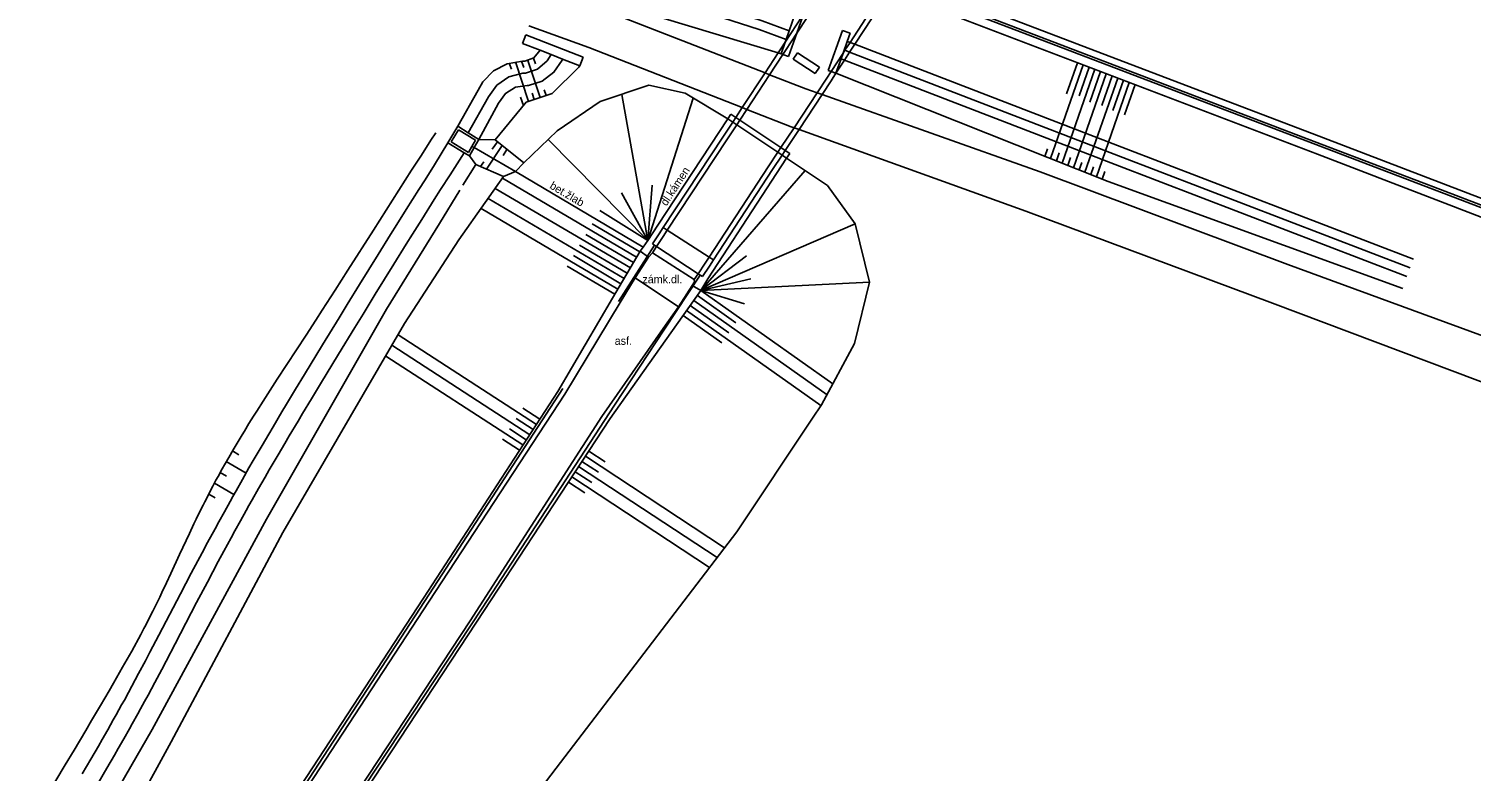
# Model space of a CAD drawing. Extents: x -541281 to -539153, y -1183881 to -1182141.
# Drawn here: x -539332 to -539214.8, y -1182543.9 to -1182483.7 of the extents above; entities that cross this region are included whole.
import ezdxf

# ---------------------------------------------------------------- set-up
doc = ezdxf.new("R2010")
doc.units = 0
for name, color, linetype in [('Vrstva 10', 7, 'Continuous'), ('Vrstva 11', 7, 'Continuous'), ('Vrstva 14', 7, 'Continuous'), ('Vrstva 15', 7, 'Continuous'), ('Vrstva 40', 7, 'Continuous'), ('Vrstva 9', 7, 'Continuous')]:
    doc.layers.add(name, color=color, linetype=linetype)

msp = doc.modelspace()

# ---------------------------------------------------------------- linework, layer by layer
at = {"layer": 'Vrstva 10'}
for p, q in [((-539226.84, -1182492.54), (-539261.27, -1182479.4)), ((-539269.89, -1182486.16), (-539269.55, -1182485.65)), ((-539269.89, -1182486.16), (-539268.1, -1182487.32)), ((-539269.55, -1182485.65), (-539267.77, -1182486.81)), ((-539267.77, -1182486.81), (-539268.1, -1182487.32)), ((-539275.2, -1182490.99), (-539274.97, -1182490.62)), ((-539297.14, -1182491.6), (-539297.94, -1182492.94)), ((-539297.07, -1182491.88), (-539297.67, -1182492.87)), ((-539295.7, -1182492.74), (-539297.07, -1182491.88)), ((-539280.88, -1182499.63), (-539275.2, -1182490.99)), ((-539274.48, -1182491.48), (-539275.29, -1182492.71)), ((-539275.2, -1182490.99), (-539274.8, -1182491.26)), ((-539274.24, -1182491.11), (-539274.48, -1182491.48)), ((-539297.67, -1182492.87), (-539296.26, -1182493.73)), ((-539189.55, -1182506.8), (-539226.84, -1182492.54)), ((-539270.43, -1182494.19), (-539276.02, -1182502.73)), ((-539271.15, -1182493.71), (-539271.93, -1182494.9)), ((-539270.8, -1182493.95), (-539271.58, -1182495.12)), ((-539270.89, -1182493.33), (-539271.15, -1182493.71)), ((-539270.55, -1182493.56), (-539270.8, -1182493.95)), ((-539270.18, -1182493.8), (-539270.43, -1182494.19)), ((-539281.71, -1182500.86), (-539280.88, -1182499.63)), ((-539280.45, -1182499.82), (-539280.12, -1182500.03)), ((-539280.12, -1182500.03), (-539276.71, -1182502.22)), ((-539280.78, -1182500.32), (-539281.33, -1182501.14)), ((-539281, -1182501.36), (-539281.33, -1182501.14)), ((-539281, -1182501.36), (-539281.32, -1182501.88)), ((-539280.45, -1182500.54), (-539281, -1182501.36)), ((-539277.62, -1182503.57), (-539281, -1182501.36)), ((-539281.64, -1182502.22), (-539282.74, -1182503.91)), ((-539281.64, -1182502.22), (-539282.32, -1182501.73)), ((-539281.32, -1182501.88), (-539281.64, -1182502.22)), ((-539277.93, -1182504.05), (-539281.32, -1182501.88)), ((-539276.71, -1182502.22), (-539276.37, -1182502.45)), ((-539277.93, -1182504.05), (-539277.62, -1182503.57)), ((-539277.04, -1182502.72), (-539277.62, -1182503.57)), ((-539277.62, -1182503.57), (-539277.27, -1182503.79)), ((-539276.7, -1182502.95), (-539277.27, -1182503.79)), ((-539276.02, -1182502.73), (-539276.84, -1182503.99)), ((-539282.74, -1182503.91), (-539283.95, -1182505.91)), ((-539282.74, -1182503.91), (-539279.21, -1182506.25)), ((-539279.21, -1182506.25), (-539278.11, -1182504.53)), ((-539278.11, -1182504.53), (-539277.92, -1182504.23)), ((-539277.4, -1182504.93), (-539278.11, -1182504.53)), ((-539277.92, -1182504.23), (-539277.93, -1182504.05)), ((-539276.84, -1182503.99), (-539277.4, -1182504.93)), ((-539283.95, -1182505.91), (-539288.43, -1182513.35)), ((-539280.45, -1182508.02), (-539279.21, -1182506.25)), ((-539285.43, -1182515.17), (-539280.45, -1182508.02)), ((-539288.43, -1182513.35), (-539299.45, -1182530.16)), ((-539296.13, -1182531.74), (-539285.43, -1182515.17)), ((-539299.45, -1182530.16), (-539310.38, -1182546.83)), ((-539307.25, -1182548.59), (-539296.13, -1182531.74))]:
    msp.add_line(p, q, dxfattribs=at)
for points in [[(-539262.66, -1182472.71), (-539265.88, -1182477.64), (-539266.18, -1182478.09), (-539266.29, -1182478.27), (-539266.68, -1182478.86), (-539269.16, -1182482.65), (-539270.55, -1182484.78), (-539270.84, -1182485.23)], [(-539262.33, -1182472.93), (-539265.5, -1182477.78), (-539265.8, -1182478.24), (-539265.91, -1182478.41), (-539266.3, -1182479), (-539269.6, -1182484.05), (-539270.52, -1182485.45)], [(-539259.03, -1182475.18), (-539261.67, -1182479.24), (-539261.97, -1182479.7), (-539262.08, -1182479.87), (-539262.47, -1182480.47), (-539265.28, -1182484.79), (-539265.7, -1182485.43), (-539265.85, -1182485.66), (-539266.82, -1182487.15), (-539267.17, -1182487.69)], [(-539258.68, -1182475.41), (-539261.27, -1182479.4), (-539261.57, -1182479.85), (-539261.68, -1182480.02), (-539262.07, -1182480.62), (-539264.89, -1182484.94), (-539265.31, -1182485.59), (-539265.72, -1182486.23), (-539266.43, -1182487.29), (-539266.82, -1182487.91)], [(-539270.84, -1182485.23), (-539271.11, -1182485.65), (-539272.18, -1182487.27), (-539274.03, -1182490.08), (-539274.56, -1182490.89)], [(-539270.52, -1182485.45), (-539270.73, -1182485.77), (-539271.81, -1182487.42), (-539273.66, -1182490.23), (-539274.24, -1182491.11)], [(-539267.17, -1182487.69), (-539267.96, -1182488.88), (-539269.82, -1182491.72), (-539270.89, -1182493.33)], [(-539266.82, -1182487.91), (-539267.55, -1182489.03), (-539269.42, -1182491.86), (-539270.55, -1182493.56)], [(-539274.56, -1182490.89), (-539274.8, -1182491.26), (-539275.62, -1182492.49)], [(-539274.97, -1182490.62), (-539274.56, -1182490.89), (-539274.24, -1182491.11), (-539270.89, -1182493.33), (-539270.55, -1182493.56), (-539270.18, -1182493.8)], [(-539295.43, -1182492.67), (-539296.28, -1182492.14), (-539297.14, -1182491.6)], [(-539274.8, -1182491.26), (-539274.48, -1182491.48), (-539271.15, -1182493.71), (-539270.8, -1182493.95), (-539270.43, -1182494.19)], [(-539297.94, -1182492.94), (-539299.02, -1182494.73), (-539299.79, -1182495.94), (-539300.3, -1182496.74), (-539301.32, -1182498.36), (-539302.08, -1182499.57), (-539302.59, -1182500.38), (-539303.6, -1182502), (-539305.11, -1182504.44), (-539306.11, -1182506.07), (-539306.78, -1182507.15), (-539308.11, -1182509.33), (-539309.58, -1182511.74), (-539310.31, -1182512.95), (-539311.04, -1182514.16), (-539311.41, -1182514.77), (-539312.13, -1182515.99), (-539312.49, -1182516.59), (-539313.03, -1182517.51), (-539313.74, -1182518.73), (-539314.09, -1182519.34), (-539314.62, -1182520.27), (-539315.14, -1182521.19), (-539315.4, -1182521.65), (-539315.63, -1182522.06), (-539316.09, -1182522.89), (-539316.55, -1182523.72), (-539316.85, -1182524.28), (-539317.45, -1182525.39), (-539317.9, -1182526.22), (-539318.78, -1182527.89), (-539319.66, -1182529.56), (-539321.41, -1182532.91), (-539322.14, -1182534.3), (-539322.5, -1182534.99), (-539323.05, -1182536.02), (-539323.6, -1182537.05), (-539323.88, -1182537.57), (-539324.21, -1182538.18), (-539324.44, -1182538.58), (-539324.88, -1182539.38), (-539325.11, -1182539.78), (-539325.56, -1182540.59), (-539326.02, -1182541.39), (-539326.32, -1182541.92), (-539326.94, -1182542.98), (-539327.64, -1182544.17)], [(-539297.94, -1182492.94), (-539296.61, -1182493.75), (-539296.19, -1182494.01)], [(-539296.26, -1182493.73), (-539295.98, -1182493.23), (-539295.7, -1182492.74)], [(-539296.19, -1182494.01), (-539295.8, -1182493.33), (-539295.43, -1182492.67)], [(-539275.62, -1182492.49), (-539280.45, -1182499.82), (-539280.78, -1182500.32)], [(-539275.29, -1182492.71), (-539280.12, -1182500.03), (-539280.45, -1182500.54)], [(-539296.61, -1182493.75), (-539297.76, -1182495.53), (-539298.53, -1182496.74), (-539299.04, -1182497.55), (-539300.06, -1182499.16), (-539300.82, -1182500.37), (-539301.32, -1182501.18), (-539302.33, -1182502.8), (-539303.83, -1182505.23), (-539304.83, -1182506.85), (-539305.5, -1182507.93), (-539306.82, -1182510.1), (-539308.29, -1182512.51), (-539309.02, -1182513.72), (-539309.75, -1182514.92), (-539310.11, -1182515.53), (-539310.83, -1182516.74), (-539311.19, -1182517.35), (-539311.73, -1182518.26), (-539312.44, -1182519.48), (-539312.79, -1182520.09), (-539313.32, -1182521), (-539313.84, -1182521.92), (-539314.09, -1182522.38), (-539314.32, -1182522.8), (-539314.78, -1182523.62), (-539315.23, -1182524.45), (-539315.53, -1182525), (-539316.13, -1182526.1), (-539316.58, -1182526.94), (-539317.46, -1182528.6), (-539318.34, -1182530.27), (-539320.09, -1182533.62), (-539320.82, -1182535.01), (-539321.18, -1182535.7), (-539321.73, -1182536.74), (-539322.29, -1182537.78), (-539322.57, -1182538.29), (-539322.9, -1182538.9), (-539323.12, -1182539.31), (-539323.57, -1182540.11), (-539323.8, -1182540.52), (-539324.25, -1182541.32), (-539324.71, -1182542.12), (-539325.02, -1182542.66), (-539325.64, -1182543.72), (-539326.33, -1182544.92)], [(-539271.93, -1182494.9), (-539276.71, -1182502.22), (-539277.04, -1182502.72)], [(-539271.58, -1182495.12), (-539276.37, -1182502.45), (-539276.7, -1182502.95)], [(-539282.32, -1182501.73), (-539282.09, -1182501.41), (-539281.71, -1182500.86)]]:
    msp.add_lwpolyline(points, dxfattribs=at)
at = {"layer": 'Vrstva 11'}
for p, q in [((-539227.03, -1182493.04), (-539261.57, -1182479.85)), ((-539272.18, -1182487.27), (-539285.9, -1182481.93)), ((-539291.37, -1182483.45), (-539286.5, -1182485.21)), ((-539265.88, -1182483.82), (-539267.05, -1182487.07)), ((-539265.26, -1182484.04), (-539265.88, -1182483.82)), ((-539291.87, -1182484.87), (-539291.6, -1182484.18)), ((-539291.6, -1182484.18), (-539286.96, -1182486)), ((-539270.55, -1182484.78), (-539270.88, -1182485.72)), ((-539269.6, -1182484.05), (-539270.27, -1182485.93)), ((-539265.5, -1182484.71), (-539265.28, -1182484.79)), ((-539265.28, -1182484.79), (-539264.89, -1182484.94)), ((-539264.89, -1182484.94), (-539243.22, -1182493.3)), ((-539287.23, -1182486.69), (-539286.96, -1182486)), ((-539286.5, -1182485.21), (-539274.03, -1182490.08)), ((-539270.88, -1182485.72), (-539270.73, -1182485.77)), ((-539270.73, -1182485.77), (-539270.27, -1182485.93)), ((-539266.01, -1182486.12), (-539265.72, -1182486.23)), ((-539265.72, -1182486.23), (-539243.76, -1182494.7)), ((-539271.81, -1182487.42), (-539272.18, -1182487.27)), ((-539266.82, -1182487.15), (-539267.05, -1182487.07)), ((-539266.43, -1182487.29), (-539266.82, -1182487.15)), ((-539268.88, -1182488.55), (-539271.81, -1182487.42)), ((-539267.96, -1182488.88), (-539268.88, -1182488.55)), ((-539295.48, -1182488.67), (-539297.14, -1182491.6)), ((-539293.82, -1182489.72), (-539295.43, -1182492.67)), ((-539267.55, -1182489.03), (-539267.96, -1182488.88)), ((-539249.84, -1182495.31), (-539267.55, -1182489.03)), ((-539274.03, -1182490.08), (-539273.66, -1182490.23)), ((-539273.66, -1182490.23), (-539270.05, -1182491.64)), ((-539270.05, -1182491.64), (-539269.82, -1182491.72)), ((-539269.82, -1182491.72), (-539269.42, -1182491.86)), ((-539269.42, -1182491.86), (-539250.99, -1182498.5)), ((-539243.22, -1182493.3), (-539219.52, -1182502.4)), ((-539229.72, -1182502.81), (-539249.84, -1182495.31)), ((-539243.76, -1182494.7), (-539220.05, -1182503.79)), ((-539250.99, -1182498.5), (-539230.96, -1182505.97)), ((-539209.46, -1182510.25), (-539229.72, -1182502.81)), ((-539230.96, -1182505.97), (-539210.81, -1182513.56))]:
    msp.add_line(p, q, dxfattribs=at)
for points in [[(-539270.47, -1182484.55), (-539272.67, -1182483.74), (-539283.71, -1182480.16)], [(-539269.73, -1182482.45), (-539269.97, -1182483.14), (-539270.22, -1182483.85), (-539270.47, -1182484.55), (-539270.55, -1182484.78)], [(-539269.16, -1182482.65), (-539269.11, -1182482.67), (-539269.6, -1182484.05)], [(-539291.87, -1182484.87), (-539290.44, -1182485.43), (-539289.56, -1182485.78), (-539288.63, -1182486.14), (-539287.23, -1182486.69)], [(-539265.26, -1182484.04), (-539265.5, -1182484.71), (-539265.85, -1182485.66)], [(-539290.44, -1182485.43), (-539290.95, -1182486.03), (-539291.68, -1182486.31), (-539291.89, -1182486.32)], [(-539291.4, -1182488.3), (-539290.28, -1182487.94), (-539289.33, -1182487.22), (-539288.67, -1182486.24), (-539288.63, -1182486.14)], [(-539265.85, -1182485.66), (-539266.01, -1182486.12), (-539266.43, -1182487.29)], [(-539291.89, -1182486.32), (-539293.12, -1182486.52), (-539294.23, -1182487.09), (-539295.1, -1182487.98), (-539295.48, -1182488.67)], [(-539293.82, -1182489.72), (-539293.27, -1182488.93), (-539292.44, -1182488.42), (-539291.49, -1182488.29), (-539291.4, -1182488.3)], [(-539189.71, -1182507.31), (-539217.34, -1182496.74), (-539227.03, -1182493.04)]]:
    msp.add_lwpolyline(points, dxfattribs=at)
at = {"layer": 'Vrstva 14'}
for p, q in [((-539271.11, -1182485.65), (-539285.68, -1182481.23)), ((-539262.07, -1182480.62), (-539227.31, -1182493.87)), ((-539270.88, -1182485.72), (-539271.11, -1182485.65)), ((-539265.7, -1182485.43), (-539265.31, -1182485.59)), ((-539265.31, -1182485.59), (-539243.49, -1182494)), ((-539244.32, -1182496.07), (-539266.43, -1182487.29)), ((-539281.62, -1182488.26), (-539285.57, -1182489.6)), ((-539278.68, -1182488.92), (-539281.62, -1182488.26)), ((-539294.64, -1182489.2), (-539296.28, -1182492.14)), ((-539291.58, -1182489.65), (-539294.11, -1182492.7)), ((-539289.46, -1182488.93), (-539291.58, -1182489.65)), ((-539285.57, -1182489.6), (-539289.07, -1182491.96)), ((-539275.2, -1182490.99), (-539278.68, -1182488.92)), ((-539289.07, -1182491.96), (-539291.77, -1182494.57)), ((-539295.8, -1182493.33), (-539295.98, -1182493.23)), ((-539295.43, -1182492.67), (-539294.11, -1182492.7)), ((-539294.11, -1182492.7), (-539291.77, -1182494.57)), ((-539295.68, -1182494.69), (-539296.19, -1182494.01)), ((-539292.45, -1182495.28), (-539295.8, -1182493.33)), ((-539267.1, -1182496.41), (-539270.43, -1182494.19)), ((-539243.49, -1182494), (-539219.78, -1182503.09)), ((-539295.68, -1182494.69), (-539296.72, -1182496.38)), ((-539293.41, -1182495.68), (-539295.68, -1182494.69)), ((-539292.45, -1182495.28), (-539293.41, -1182495.68)), ((-539291.77, -1182494.57), (-539292.45, -1182495.28)), ((-539282.09, -1182501.41), (-539292.45, -1182495.28)), ((-539296.96, -1182496.78), (-539298.63, -1182499.48)), ((-539293.41, -1182495.68), (-539294.9, -1182497.79)), ((-539264.87, -1182499.51), (-539267.1, -1182496.41)), ((-539220.4, -1182504.78), (-539244.32, -1182496.07)), ((-539294.9, -1182497.79), (-539297.04, -1182500.82)), ((-539298.63, -1182499.48), (-539302.93, -1182506.44)), ((-539263.71, -1182504.26), (-539264.87, -1182499.51)), ((-539297.04, -1182500.82), (-539301.45, -1182507.61)), ((-539284.56, -1182505.55), (-539282.32, -1182501.73)), ((-539277.4, -1182504.93), (-539279.84, -1182508.38)), ((-539264.91, -1182509.24), (-539263.71, -1182504.26)), ((-539289.02, -1182513.13), (-539284.56, -1182505.55)), ((-539302.93, -1182506.44), (-539312.66, -1182523.5)), ((-539301.45, -1182507.61), (-539311.34, -1182524.58)), ((-539279.84, -1182508.38), (-539284.75, -1182515.31)), ((-539267.59, -1182514.22), (-539264.91, -1182509.24)), ((-539299.91, -1182529.92), (-539289.02, -1182513.13)), ((-539268.32, -1182515.3), (-539267.59, -1182514.22)), ((-539284.75, -1182515.31), (-539295.62, -1182531.85)), ((-539274.47, -1182524.51), (-539268.32, -1182515.3)), ((-539312.66, -1182523.5), (-539321.95, -1182540.58)), ((-539311.34, -1182524.58), (-539320.4, -1182541.56)), ((-539287.38, -1182541.4), (-539274.47, -1182524.51)), ((-539310.89, -1182546.64), (-539299.91, -1182529.92)), ((-539295.62, -1182531.85), (-539306.88, -1182548.96)), ((-539321.95, -1182540.58), (-539331.97, -1182557.91)), ((-539320.4, -1182541.56), (-539330.04, -1182559.14)), ((-539298.24, -1182555.56), (-539287.38, -1182541.4))]:
    msp.add_line(p, q, dxfattribs=at)
for points in [[(-539270.22, -1182483.85), (-539272.42, -1182483.03), (-539283.38, -1182479.47)], [(-539291.63, -1182487.28), (-539290.66, -1182486.96), (-539289.88, -1182486.3), (-539289.56, -1182485.78)], [(-539294.64, -1182489.2), (-539293.95, -1182488.25), (-539292.98, -1182487.59), (-539291.85, -1182487.29), (-539291.63, -1182487.28)], [(-539287.23, -1182486.69), (-539287.3, -1182486.81), (-539289.46, -1182488.93)], [(-539298.91, -1182492.13), (-539299.31, -1182492.74), (-539300.09, -1182493.95), (-539300.88, -1182495.16), (-539301.4, -1182495.97), (-539302.44, -1182497.59), (-539303.99, -1182500.03), (-539306.06, -1182503.28), (-539307.1, -1182504.9), (-539308.14, -1182506.53), (-539308.66, -1182507.33), (-539309.45, -1182508.55), (-539311.79, -1182512.13), (-539312.57, -1182513.32), (-539312.95, -1182513.92), (-539313.46, -1182514.72), (-539313.72, -1182515.13), (-539314.09, -1182515.73), (-539314.46, -1182516.34), (-539314.65, -1182516.64), (-539314.98, -1182517.18), (-539315.14, -1182517.45), (-539315.38, -1182517.86), (-539315.74, -1182518.48), (-539316.09, -1182519.09), (-539316.26, -1182519.41), (-539316.6, -1182520.03), (-539316.77, -1182520.34), (-539317.02, -1182520.81), (-539317.24, -1182521.23), (-539317.39, -1182521.51), (-539317.68, -1182522.08), (-539317.82, -1182522.36), (-539318.1, -1182522.93), (-539318.37, -1182523.5), (-539318.56, -1182523.88), (-539318.92, -1182524.65), (-539319.19, -1182525.22), (-539319.72, -1182526.37), (-539320.44, -1182527.91), (-539320.8, -1182528.67), (-539321.16, -1182529.44), (-539321.34, -1182529.82), (-539321.71, -1182530.58), (-539321.9, -1182530.96), (-539322.19, -1182531.52), (-539322.47, -1182532.09), (-539322.62, -1182532.37), (-539322.88, -1182532.87), (-539323.06, -1182533.2), (-539323.42, -1182533.87), (-539323.61, -1182534.2), (-539323.98, -1182534.85), (-539324.35, -1182535.51), (-539324.6, -1182535.95), (-539325.1, -1182536.82), (-539325.45, -1182537.43), (-539326.16, -1182538.63), (-539326.87, -1182539.84), (-539327.34, -1182540.64), (-539328.29, -1182542.24), (-539329.01, -1182543.44), (-539330.44, -1182545.84)], [(-539227.31, -1182493.87), (-539217.67, -1182497.58), (-539171.44, -1182515.37), (-539152.7, -1182522.58)]]:
    msp.add_lwpolyline(points, dxfattribs=at)
at = {"layer": 'Vrstva 15'}
for p, q in [((-539290.98, -1182486.06), (-539290.82, -1182486.52)), ((-539292.95, -1182486.47), (-539292.78, -1182486.97)), ((-539292.46, -1182486.36), (-539291.39, -1182489.58)), ((-539291.95, -1182486.32), (-539291.78, -1182486.83)), ((-539291.44, -1182486.27), (-539290.44, -1182489.26)), ((-539248.99, -1182494.22), (-539246.34, -1182486.62)), ((-539248.06, -1182494.59), (-539245.4, -1182486.97)), ((-539247.69, -1182488.96), (-539246.8, -1182486.44)), ((-539247.13, -1182494.96), (-539244.47, -1182487.33)), ((-539246.68, -1182489.12), (-539245.87, -1182486.79)), ((-539245.81, -1182489.65), (-539244.93, -1182487.15)), ((-539246.2, -1182495.33), (-539243.53, -1182487.69)), ((-539245.27, -1182495.7), (-539242.6, -1182488.04)), ((-539244.83, -1182489.9), (-539244, -1182487.51)), ((-539243.93, -1182490.33), (-539243.07, -1182487.86)), ((-539242.98, -1182490.66), (-539242.13, -1182488.22)), ((-539292.03, -1182489.24), (-539291.81, -1182489.92)), ((-539291.09, -1182488.91), (-539290.92, -1182489.42)), ((-539290.12, -1182488.65), (-539289.97, -1182489.1)), ((-539281.71, -1182500.86), (-539283.82, -1182489.01)), ((-539281.71, -1182500.86), (-539278.01, -1182489.31)), ((-539294.81, -1182495.07), (-539293.53, -1182493.17)), ((-539294.33, -1182493.46), (-539293.92, -1182492.86)), ((-539281.71, -1182500.86), (-539289.8, -1182492.66)), ((-539293.45, -1182493.96), (-539293.14, -1182493.49)), ((-539249.45, -1182494.04), (-539249.24, -1182493.42)), ((-539248.52, -1182494.41), (-539248.3, -1182493.76)), ((-539247.59, -1182494.78), (-539247.37, -1182494.13)), ((-539295.28, -1182494.87), (-539295.01, -1182494.48)), ((-539277.39, -1182504.92), (-539268.92, -1182495.2)), ((-539246.66, -1182495.14), (-539246.45, -1182494.54)), ((-539245.73, -1182495.51), (-539245.51, -1182494.88)), ((-539244.8, -1182495.88), (-539244.59, -1182495.27)), ((-539283.11, -1182503.09), (-539294.09, -1182496.64)), ((-539282.61, -1182502.23), (-539293.51, -1182495.81)), ((-539281.71, -1182500.86), (-539281.35, -1182496.37)), ((-539283.62, -1182503.95), (-539294.67, -1182497.46)), ((-539281.71, -1182500.86), (-539283.84, -1182497.01)), ((-539284.13, -1182504.81), (-539295.24, -1182498.28)), ((-539281.71, -1182500.86), (-539285.61, -1182498.43)), ((-539282.35, -1182501.8), (-539286.23, -1182499.52)), ((-539277.39, -1182504.92), (-539264.87, -1182499.51)), ((-539283.37, -1182503.52), (-539287.24, -1182501.24)), ((-539282.86, -1182502.66), (-539286.74, -1182500.38)), ((-539283.88, -1182504.38), (-539287.75, -1182502.1)), ((-539277.39, -1182504.92), (-539273.69, -1182502.13)), ((-539284.38, -1182505.24), (-539288.26, -1182502.96)), ((-539277.39, -1182504.92), (-539273.34, -1182503.98)), ((-539277.39, -1182504.92), (-539263.71, -1182504.26)), ((-539277.39, -1182504.92), (-539266.67, -1182512.51)), ((-539277.39, -1182504.92), (-539273.86, -1182506)), ((-539278.26, -1182506.14), (-539275.12, -1182508.36)), ((-539277.97, -1182505.74), (-539267.15, -1182513.4)), ((-539277.68, -1182505.33), (-539274.55, -1182507.55)), ((-539278.84, -1182506.96), (-539275.7, -1182509.18)), ((-539278.55, -1182506.55), (-539267.64, -1182514.28)), ((-539291.29, -1182516.64), (-539302.48, -1182509.38)), ((-539290.75, -1182515.8), (-539301.98, -1182508.52)), ((-539291.84, -1182517.47), (-539302.99, -1182510.25)), ((-539291.02, -1182516.22), (-539292.4, -1182515.32)), ((-539290.48, -1182515.38), (-539291.85, -1182514.48)), ((-539291.57, -1182517.05), (-539292.94, -1182516.16)), ((-539292.11, -1182517.89), (-539293.49, -1182517)), ((-539315.94, -1182518.82), (-539314.33, -1182519.76)), ((-539315.44, -1182517.96), (-539314.92, -1182518.26)), ((-539287.05, -1182518.8), (-539285.71, -1182519.68)), ((-539286.77, -1182518.39), (-539275.47, -1182525.82)), ((-539286.5, -1182517.97), (-539285.16, -1182518.85)), ((-539316.42, -1182519.7), (-539315.91, -1182520)), ((-539287.87, -1182520.06), (-539276.69, -1182527.41)), ((-539287.59, -1182519.64), (-539286.26, -1182520.52)), ((-539287.32, -1182519.22), (-539276.08, -1182526.61)), ((-539316.9, -1182520.58), (-539315.32, -1182521.5)), ((-539288.14, -1182520.48), (-539286.81, -1182521.35)), ((-539317.36, -1182521.47), (-539316.85, -1182521.77))]:
    msp.add_line(p, q, dxfattribs=at)
at = {"layer": 'Vrstva 9'}
for p, q in [((-539261.68, -1182480.02), (-539227.1, -1182493.22)), ((-539227.1, -1182493.22), (-539189.79, -1182507.49)), ((-539281.16, -1182501.25), (-539284.09, -1182505.83)), ((-539280.35, -1182508.08), (-539277.44, -1182503.68)), ((-539284.42, -1182514.23), (-539280.35, -1182508.08)), ((-539288.61, -1182512.88), (-539299.42, -1182529.55)), ((-539295.15, -1182530.71), (-539284.42, -1182514.23)), ((-539299.42, -1182529.55), (-539310.36, -1182546.34)), ((-539306.72, -1182548.21), (-539295.15, -1182530.71))]:
    msp.add_line(p, q, dxfattribs=at)

# ---------------------------------------------------------------- texts
at = {"layer": 'Vrstva 40'}
for s, rotation, p in [('dl.kámen', 56.6959, (-539280.19, -1182498.12)), ('bet.žlab', 329.4296, (-539289.73, -1182496.6))]:
    msp.add_text(s, height=0.65, rotation=rotation, dxfattribs=at).set_placement(p)
for s, p in [('zámk.dl.', (-539282.14, -1182504.34)), ('asf.', (-539284.39, -1182509.34))]:
    msp.add_text(s, height=0.65, dxfattribs=at).set_placement(p)

doc.saveas('drawing.dxf')
